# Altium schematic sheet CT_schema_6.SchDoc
size 277 x 170 mm
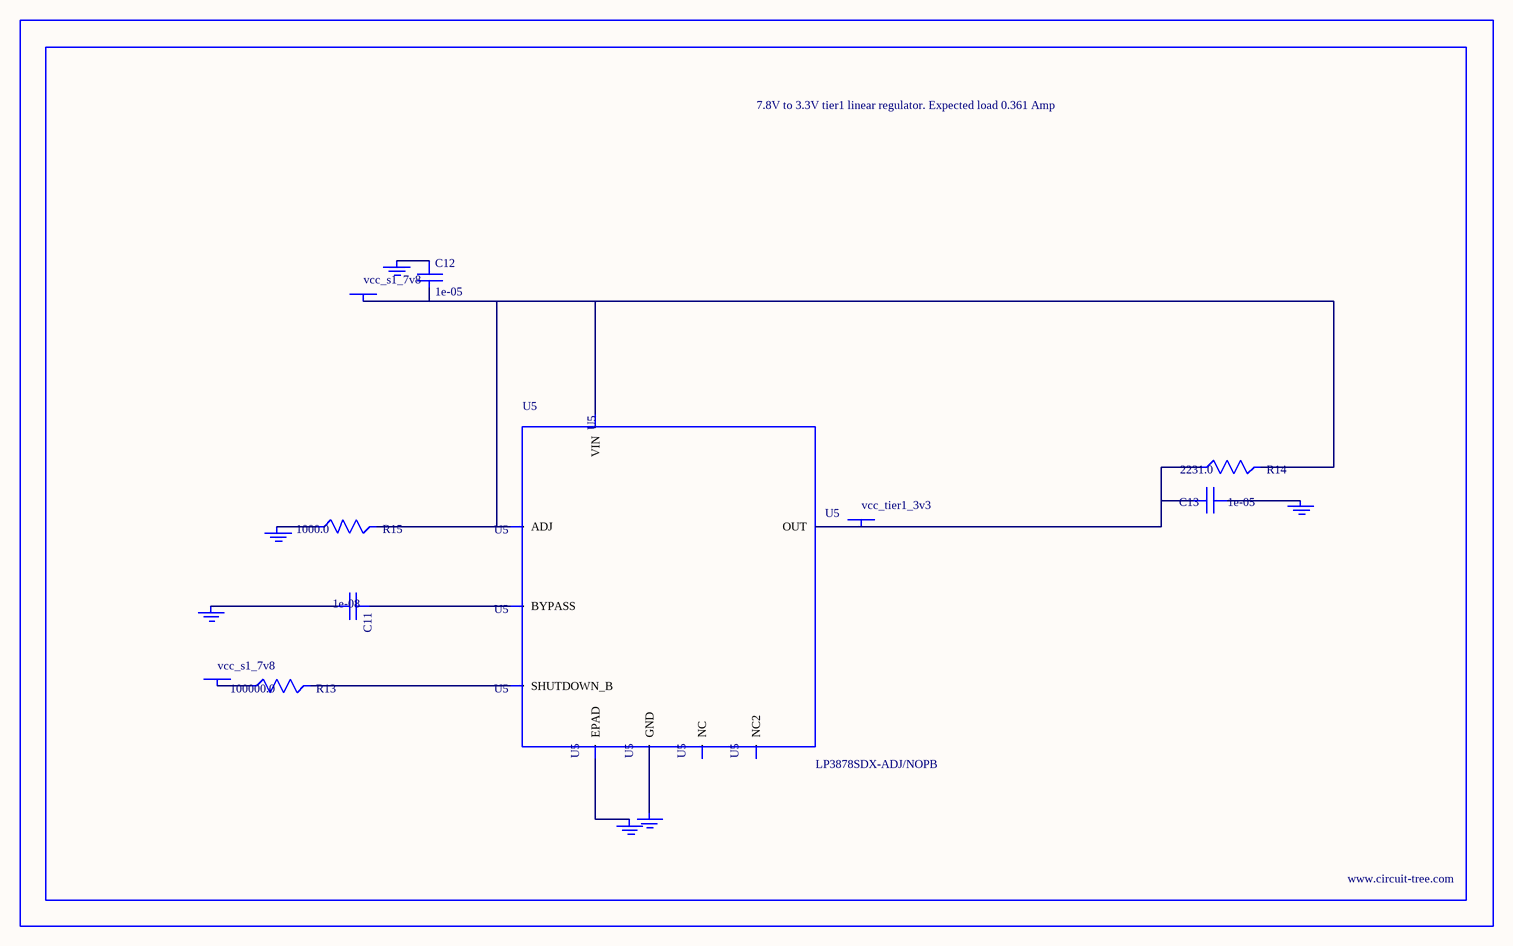
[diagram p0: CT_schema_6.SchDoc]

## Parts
BORDER5  (no value)
C11  1e-08  [C0402]
C12  1e-05  [C1206]
C13  1e-05  [C1210]
GND_INSTANCE_5_0  (no value)
GND_INSTANCE_5_1  (no value)
GND_INSTANCE_5_2  (no value)
GND_INSTANCE_5_3  (no value)
GND_INSTANCE_5_4  (no value)
GND_INSTANCE_5_5  (no value)
POWER_INSTANCE_5_0  vcc_s1_7v8
POWER_INSTANCE_5_1  vcc_s1_7v8
POWER_INSTANCE_5_2  vcc_tier1_3v3
R13  100000.0  [R0603]
R14  2231.0  [R0603]
R15  1000.0  [R0603]
U5  LP3878SDX-ADJ/NOPB  [WSON-8]

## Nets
NetC11_1: C11.1 U5.1(BYPASS)
NetC11_2: C11.2 GND_INSTANCE_5_0.0(GND)
NetC12_1: C12.1 GND_INSTANCE_5_1.0(GND)
NetC12_2: C12.2 POWER_INSTANCE_5_0.0(PWR) R14.2 R15.2 U5.4(VIN) U5.6(ADJ)
NetC13_1: C13.1 GND_INSTANCE_5_2.0(GND)
NetC13_2: C13.2 POWER_INSTANCE_5_2.0(PWR) R14.1 U5.5(OUT)
NetGND_INSTANCE_5_3_0: GND_INSTANCE_5_3.0(GND) R15.1
NetGND_INSTANCE_5_4_0: GND_INSTANCE_5_4.0(GND) U5.PAD(EPAD)
NetGND_INSTANCE_5_5_0: GND_INSTANCE_5_5.0(GND) U5.3(GND)
NetPOWER_INSTANCE_5_1_0: POWER_INSTANCE_5_1.0(PWR) R13.1
NetR13_2: R13.2 U5.8(SHUTDOWN_B)

Not connected (* = marked no-connect by the designer): U5 2(NC) 7(NC2)

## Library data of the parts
BORDER5 = BORDER_PAGE5
C11 = C0402C103K3RAC
C12 = C1206C106K3RACTU
C13 = GRM32DR61E106MA12L
GND_INSTANCE_5_0-GND_INSTANCE_5_5 = GND
POWER_INSTANCE_5_0-POWER_INSTANCE_5_2 = PWR
R13 = RC0603JR-07100KL
R14 = R14
R15 = RC0603JR-071KL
